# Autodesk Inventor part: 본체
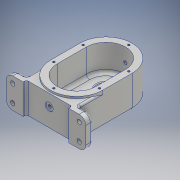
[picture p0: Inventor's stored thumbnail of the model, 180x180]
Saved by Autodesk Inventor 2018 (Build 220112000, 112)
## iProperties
Created: 2021-05
Part Number: 본체
Material: 알루미늄 6061
Document SubType Name: Modeling
Designer: Admin
Density: 2.7 g/cm^3
Appearance: 알루미늄 - 평지
Mass: 755.996 g
Surface Area: 583.122 cm^2
Volume: 279.999 cm^3
Author: Admin
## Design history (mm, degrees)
sketch "스케치1"
  geometry: L1 (0, -22.5)-(0, 22.5); L2 (40, -22.5)-(40, 22.5); L3 (-40, 22.5)-(-40, -22.5); L4 (-85.4, 0)-(85.4, 0) reference; L5 (0, -95.9)-(0, 88.9) reference; A1 r 40 centre (0, -22.5) between (-40, -22.5) and (40, -22.5); A2 r 40 centre (0, 22.5) between (40, 22.5) and (-40, 22.5); 1 further point
  constraints: 8 end point, 4 point on circle, 4 tangent, 2 centre point, 1 collinear, 1 midpoint, 1 parallel
  dimensions: "d0" = 45 distance of L1.start L1.end; "d1" = 80 distance between parallel lines of L3 L2
extrude "돌출1" new body sketch "스케치1" stored distance "d2" = 49; taper "d3" = 0 deg
node "작업 평면2"
sketch "스케치10"
  geometry: L1 (-85.4, 0)-(85.4, 0) reference; L2 (40, 22.5)-(40, -22.5) reference; L3 (-40, -22.5)-(-40, 22.5) reference; L4 (0, -95.9)-(0, 88.9) reference; L5 (-40, -22.5)-(-40, -59.5); L6 (-40, -59.5)-(-61, -59.5); L7 (-61, -59.5)-(-61, -69.5); L8 (-61, -69.5)-(0, -69.5); L9 (40, -22.5)-(40, -59.5); L10 (40, -59.5)-(61, -59.5); L11 (61, -59.5)-(61, -69.5); L12 (61, -69.5)-(0, -69.5); L13 (-40, -22.5)-(40, -22.5); A1 r 40 centre (0, -22.5) between (-40, -22.5) and (40, -22.5) reference; A2 r 40 centre (0, 22.5) between (40, 22.5) and (-40, 22.5) reference; 1 further point
  constraints: 18 end point, 4 symmetric about line, 3 perpendicular, 1 horizontal, 1 horizontal alignment, 1 point on line, 1 vertical
  dimensions: "d47" = 10 distance of L6.end L7.end; "d48" = 47 distance from line of A1.centre L8; "d49" = 61 distance of L7.end L8.end; "d50" = 40 distance between parallel lines of L4 L5
extrude "돌출8" join sketch "스케치10" distance "d51" = 46; taper "d52" = 0 deg
sketch "스케치2"
  geometry: L1 (40, -22.5)-(40, 22.5) reference; L2 (-40, 22.5)-(-40, -22.5) reference; L3 (0, -22.5)-(0, 22.5); L4 (-30, -22.5)-(-30, 22.5); L5 (30, 22.5)-(30, -22.5); A1 r 40 centre (0, 22.5) between (40, 22.5) and (-40, 22.5) reference; A2 r 40 centre (0, -22.5) between (-40, -22.5) and (40, -22.5) reference; A3 r 30 centre (0, -22.5) between (-30, -22.5) and (30, -22.5); A4 r 30 centre (0, 22.5) between (30, 22.5) and (-30, 22.5); 2 further points
  constraints: 8 end point, 4 point on circle, 4 tangent, 2 centre point, 1 midpoint, 1 parallel, 1 vertical
  dimensions: "d4" = 30 radius of A4
extrude "돌출2" cut sketch "스케치2" distance "d5" = 41; taper "d6" = 0 deg
sketch "스케치3"
  geometry: L1 (-40, 22.5)-(-40, -59.5) reference; L2 (40, -59.5)-(40, 22.5) reference; L3 (0, -22.5)-(0, 22.5); L4 (-26, -22.5)-(-26, 22.5); L5 (26, 22.5)-(26, -22.5); L6 (-40, -59.5)-(-61, -59.5) reference; L7 (-61, -59.5)-(-61, -69.5) reference; L8 (-61, -69.5)-(61, -69.5) reference; L9 (61, -69.5)-(61, -59.5) reference; L10 (61, -59.5)-(40, -59.5) reference; A1 r 40 centre (0, 22.5) between (40, 22.5) and (-40, 22.5) reference; A2 r 26 centre (0, -22.5) between (-26, -22.5) and (26, -22.5); A3 r 26 centre (0, 22.5) between (26, 22.5) and (-26, 22.5); 2 further points
  constraints: 8 end point, 4 point on circle, 4 tangent, 2 centre point, 1 midpoint, 1 parallel, 1 vertical
  dimensions: "d7" = 52 distance between parallel lines of L5 L4
extrude "돌출3" join sketch "스케치3" distance "d8" = 11; taper "d9" = 0 deg
sketch "스케치4"
  geometry: L1 (-26, 22.5)-(-26, -22.5) reference; L2 (26, -22.5)-(26, 22.5) reference; L3 (-26, 22.5)-(-26, -22.5) reference; L4 (-26, -7.5)-(26, -7.5); L5 (-26, 22.5)-(-26, -7.5); L6 (26, 22.5)-(26, -22.5) reference; L7 (26, 22.5)-(26, -7.5); L8 (40, 22.5)-(40, -22.5) reference; A1 r 26 centre (0, -22.5) between (-26, -22.5) and (26, -22.5) reference; A2 r 26 centre (0, 22.5) between (26, 22.5) and (-26, 22.5) reference; 1 further point
  constraints: 6 end point, 2 point on line, 1 collinear, 1 parallel, 1 perpendicular
  dimensions: "d10" = 30 distance from line of L4 A2.centre
extrude "돌출4" cut sketch "스케치4" distance "d11" = 3; taper "d12" = 0 deg
sketch "스케치6"
  geometry: C1 r 11 at (0, 22.5); A1 r 26 centre (0, 22.5) between (26, 22.5) and (-26, 22.5) reference; 1 further point
  constraints: 1 centre point, 1 coincident
  dimensions: "d15" = 22 diameter of C1
extrude "돌출5" cut sketch "스케치6" extent not by distance; stored distance "d16" = 4; taper "d17" = 0 deg
sketch "스케치7"
  geometry: C1 r 11 at (0, 22.5) reference; C2 r 14 at (0, 22.5); 1 further point
  constraints: 1 centre point, 1 coincident
  dimensions: "d18" = 28 diameter of C2
extrude "돌출6" cut sketch "스케치7" distance "d19" = 4; taper "d20" = 0 deg
sketch "스케치8"
  geometry: L1 (-30, -22.5)-(-30, 22.5) reference; L2 (30, 22.5)-(30, -22.5) reference; C1 r 14 at (0, 22.5); C2 r 14 at (0, -22.5); A1 r 30 centre (0, -22.5) between (-30, -22.5) and (30, -22.5) reference; A2 r 30 centre (0, 22.5) between (30, 22.5) and (-30, 22.5) reference; 1 further point
  constraints: 2 centre point, 2 coincident
  dimensions: "d21" = 28 diameter of C2; "d22" = 28 diameter of C1 (= d21)
extrude "돌출7" cut sketch "스케치8" distance "d23" = 8; taper "d24" = 0 deg
sketch "스케치11"
  geometry: L1 (-85.4, 0)-(85.4, 0) reference; L2 (0, -95.9)-(0, 88.9) reference; L3 (-61, -69.5)-(61, -69.5) reference; L4 (-35, -64.5)-(35, -64.5); L5 (35, -64.5)-(35, -69.5); L6 (35, -69.5)-(-35, -69.5); L7 (-35, -69.5)-(-35, -64.5); 1 further point
  constraints: 8 end point, 2 parallel, 1 horizontal, 1 perpendicular, 1 point on line, 1 other
  dimensions: "d53" = 70 distance of L4.start L4.end; "d54" = 5 distance of L4.end L5.end
extrude "돌출9" cut sketch "스케치11" extent not by distance; stored distance "d55" = 48; taper "d56" = 0 deg
sketch "스케치12"
  geometry: C1 r 14 at (0, 0) reference; C2 r 10 at (0, 0); 1 further point
  constraints: 1 centre point, 1 coincident
  dimensions: "d57" = 20 diameter of C2
extrude "돌출10" cut sketch "스케치12" distance "d58" = 4; taper "d59" = 0 deg
sketch "스케치14"
  geometry: L1 (-30, -22.5)-(-30, 22.5) reference; L2 (30, 22.5)-(30, -22.5) reference; L3 (40, -22.5)-(40, 22.5) reference; L4 (-40, 22.5)-(-40, -22.5) reference; L5 (0, -22.5)-(0, 22.5); L6 (35, -22.5)-(35, 22.5); L7 (-35, 22.5)-(-35, -22.5); L8 (-85.4, 0)-(85.4, 0) reference; A1 r 30 centre (0, -22.5) between (-30, -22.5) and (30, -22.5) reference; A2 r 30 centre (0, 22.5) between (30, 22.5) and (-30, 22.5) reference; A3 r 40 centre (0, 22.5) between (40, 22.5) and (-40, 22.5) reference; A4 r 40 centre (0, -22.5) between (-40, -22.5) and (40, -22.5) reference; A5 r 35 centre (0, -22.5) between (-35, -22.5) and (35, -22.5); A6 r 35 centre (0, 22.5) between (35, 22.5) and (-35, 22.5); 7 further points
  constraints: 8 end point, 5 point on circle, 4 tangent, 3 symmetric about line, 2 centre point, 2 coincident, 1 midpoint, 1 parallel, 1 vertical
  dimensions: "d60" = 35 radius of A6
hole "구멍1" sketch "스케치14" at (0, 57.5), (-35, 22.5), (35, 22.5), (0, -57.5), (-35, -22.5), (35, -22.5) diameter "d61" = 3.242; stored, may be unused: countersink angle "d65" = 90 deg, drill point angle "d67" = 118 deg; dims "d62" = 8, "d63" = 4, "d64" = 2, "d66" = 10
sketch "스케치15" dims "d68" = 40
  geometry: L1 (0, -95.9)-(0, 88.9) reference; C1 r 14 at (0, 22.5) reference; 5 further points
  constraints: 1 coincident, 1 point on line, 1 vertical alignment, 6 other
  dimensions: "d71" = 360 deg dimension on C1.centre point (0, 42.5) (derived)
hole "구멍2" sketch "스케치15" at (0, 42.5), (-17.321, 12.5), (17.321, 12.5) diameter "d73" = 3.242; stored, may be unused: countersink angle "d77" = 90 deg, drill point angle "d79" = 118 deg; dims "d74" = 8, "d75" = 4, "d76" = 2, "d78" = 10
node "작업 평면5"
  node "작업 평면4"
sketch "스케치16"
  geometry: L1 (40, 24.5)-(-40, 24.5) reference; L2 (0, -47.5)-(0, 36.5) reference; C1 r 6 at (0, 3.5)
  constraints: 1 centre point, 1 point on line
  dimensions: "d82" = 12 diameter of C1; "d121" = 21 distance from line of L1 C1.centre
extrude "돌출11" join sketch "스케치16" stored distance "d83" = 4; taper "d84" = 0 deg
sketch "스케치17"
  geometry: L1 (75, 3)-(-5, 3) reference; L2 (35, -69)-(35, 15) reference; 2 further points
  constraints: 1 point on line
  dimensions: "d85" = 21 distance from line of point (35, -18) L1
hole "구멍3" sketch "스케치17" at (35, -18) diameter "d86" = 4.917; stored, may be unused: countersink angle "d90" = 90 deg, drill point angle "d92" = 118 deg; dims "d87" = 12, "d88" = 12, "d89" = 1, "d91" = 17.1
sketch "스케치18"
  geometry: C1 r 6 at (0, 0) reference; 2 further points
  constraints: 1 coincident
hole "구멍4" sketch "스케치18" at (0, 0) diameter "d93" = 4.917; stored, may be unused: countersink angle "d97" = 90 deg, drill point angle "d99" = 118 deg; dims "d94" = 17, "d95" = 12, "d96" = 1, "d98" = 18
chamfer "모따기1" distance "d100" = 1; stored, may be unused: second distance "d101" = 2, angle "d102" = 45 deg
fillet "모깎기1" dims "d103" = 10, "d111" = 5, "d112" = 3
sketch "스케치20"
  geometry: A1 r 10 centre (-91, 36) between (-91, 46) and (-101, 36) reference; A2 r 10 centre (-91, 10) between (-101, 10) and (-91, 0) reference; A3 r 10 centre (11, 10) between (11, 0) and (21, 10) reference; A4 r 10 centre (11, 36) between (21, 36) and (11, 46) reference; 5 further points
  constraints: 4 coincident
hole "구멍5" sketch "스케치20" at (-91, 36), (-91, 10), (11, 10), (11, 36) diameter "d104" = 6.6; stored, may be unused: countersink angle "d108" = 90 deg, drill point angle "d110" = 118 deg; dims "d105" = 12, "d106" = 11, "d107" = 2, "d109" = 17.1
sketch "스케치21"
  geometry: L1 (0, -96.5)-(0, 92.5) reference; L2 (6, -64.5)-(-6, -64.5) reference; L3 (35, -69.5)-(51, -69.5) reference; 2 further points
  constraints: 1 point on line, 1 other
  dimensions: "d120" = 12 distance from line of L3 point (0, -57.5)
feature "엠보싱1" sketch "스케치21" dims "d0" = 45, "d1" = 80, "d5" = 41, "d114" = 0.5, "d115" = 0
fillet "모깎기2" dims "d116" = 3
fillet "모깎기3" dims "d117" = 3
fillet "모깎기4" dims "d118" = 3, "d119" = 0.3
node "솔리드1"
node "투영된 루프1"
node "투영된 루프2"
node "투영된 루프3"
node "투영된 루프5"
node "투영된 루프6"
node "투영된 루프7"
other parameters: "d29" = -3, "d81" = 3
